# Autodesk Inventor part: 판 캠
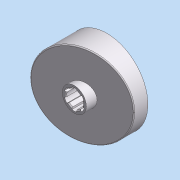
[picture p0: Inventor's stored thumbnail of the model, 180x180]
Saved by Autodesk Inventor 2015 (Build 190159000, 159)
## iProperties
Created: 2012-05
Part Number: 판 캠
Document SubType Name: 모델링
Designer: SeoGD™
Material: 일반
Appearance: 알루미늄 - 평지
변환 표준: STEP AP214IS
파일 이름: C:\Users\SeoGD\Desktop\?쒗뿕\??stp
전처리기: Build: 253, Release: 2010 SP1 - Date: Wed 07/29/2009
전송 단위: 밀리미터
불확실성: 0.01
Author: SeoGD™
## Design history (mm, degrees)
node "작업 평면4"
sketch "스케치1"
  geometry: C1 r 44.5 at (0, 0); 1 further point
  constraints: 1 centre point, 1 coincident
  dimensions: "d25" = 89 diameter of C1
extrude "돌출1" new body sketch "스케치1" distance "d1" = 40; taper "d2" = 0 deg
sketch "스케치2"
  geometry: L1 (-44.5, 15)-(44.5, 38.847); L2 (-44.5, 0)-(-44.5, 40) reference; L3 (-44.5, 40)-(44.5, 40) reference; L4 (44.5, 0)-(44.5, 40) reference; 1 further point
  constraints: 2 end point, 2 point on line
  dimensions: "d26" = 15 distance of L2.start L1.start; "d27" = 75 deg angle of L1 L2
extrude "돌출2" cut sketch "스케치2" stored distance "d5" = 40; taper "d6" = 0 deg
node "작업 평면1"
sketch "스케치3"
  geometry: C1 r 13 at (0, 0); 1 further point
  constraints: 1 centre point, 1 coincident
  dimensions: "d9" = 26 diameter of C1
extrude "돌출3" join sketch "스케치3" distance "d10" = 38; taper "d11" = 0 deg
hole "구멍1" diameter "d14" = 18; stored, may be unused: countersink angle "d18" = 90 deg, drill point angle "d20" = 118 deg; dims "d12" = 10, "d13" = 10, "d15" = 6, "d16" = 4, "d17" = 2, "d19" = 8
feature "쉘2" dims "d29" = 5
sketch "스케치6"
  geometry: C1 r 17.5 at (0, 0); C2 r 14 at (0, 0) reference; 1 further point
  constraints: 1 centre point, 1 coincident
  dimensions: "d28" = 35 diameter of C1
extrude "돌출4" join sketch "스케치6" stored distance "d30" = 38; taper "d31" = 0 deg
fillet "모깎기1" dims "d32" = 3
chamfer "모따기1" distance "d21" = 1; stored, may be unused: second distance "d22" = 2, angle "d23" = 45 deg
sketch "스케치7"
  geometry: L1 (-12.374, 12.374)-(-27.931, 27.931); A1 r 39.5 centre (0, 0) between (-27.931, 27.931) and (0, 39.5) reference; 2 further points
  constraints: 2 end point, 2 point on circle, 1 point on line, 1 vertical alignment, 2 other
  dimensions: "d33" = 45 deg dimension on point (0, 0) L1.start A1.end
feature "리브1" sketch "스케치7" dims "d34" = 5, "d35" = 1, "d36" = 0
fillet "모깎기2" dims "d37" = 3
sketch "스케치8"
  geometry: L1 (2.5, 10.712)-(2.5, 8.646); L2 (-2.5, 10.712)-(-2.5, 8.646); A1 r 11 centre (0, 0) between (2.5, 10.712) and (-2.5, 10.712); A2 r 9 centre (0, 0) between (2.5, 8.646) and (-2.5, 8.646) reference; 1 further point
  constraints: 4 end point, 4 point on circle, 2 parallel, 1 centre point, 1 coincident, 1 vertical
  dimensions: "d41" = 22 diameter of A1; "d42" = 5 distance between parallel lines of L1 L2
extrude "돌출5" cut sketch "스케치8" stored distance "d43" = 38; taper "d44" = 0 deg
fillet "모깎기3" dims "d48" = 1
node "솔리드1"
node "솔리드 본체"
node "곡면 본체"
pattern_circular "원형 패턴1" dims angle "d39" = 360 deg
pattern_circular "원형 패턴2" dims angle "d46" = 360 deg
node "솔리드2"
